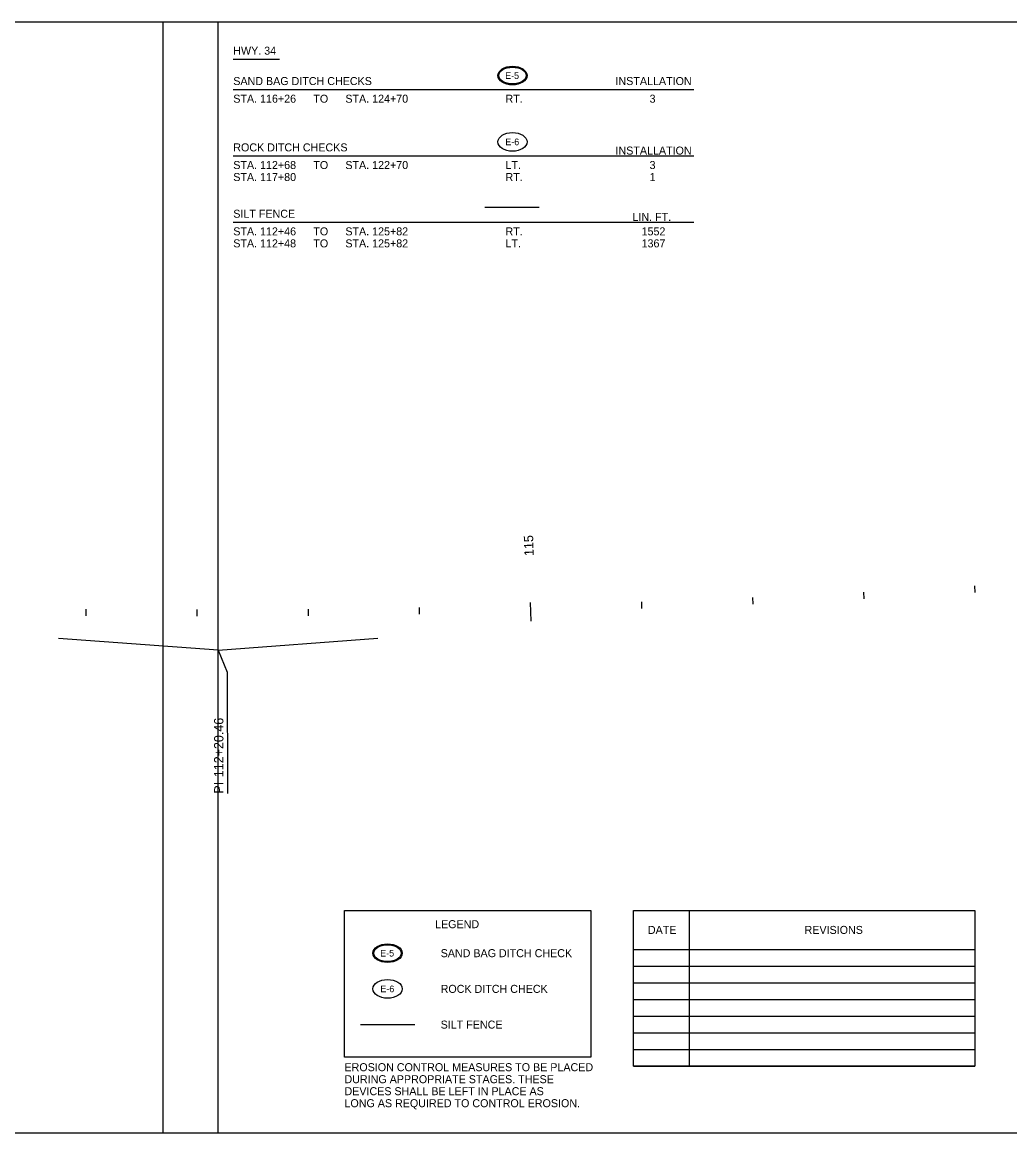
# Model space of a CAD drawing. Extents: x 1806834 to 1810084, y 678065 to 679314.
# Drawn here: x 1808308 to 1809196, y 678065 to 679065 of the extents above; entities that cross this region are included whole.
import ezdxf

# ---------------------------------------------------------------- set-up
doc = ezdxf.new("R2010")
doc.units = 0
for name, color, linetype in [('_CG DITCH CHECK', 7, 'Continuous'), ('Default', 7, 'Continuous'), ('DSN_DRFT_Guideline-No-Plot', 7, 'Continuous'), ('DSN_RDWY_Alignment Annotation', 7, 'Continuous'), ('Erosion Legend', 7, 'Continuous'), ('R_Border Notes', 7, 'Continuous')]:
    doc.layers.add(name, color=color, linetype=linetype)

# ---------------------------------------------------------------- blocks, each defined once
blk = doc.blocks.new('E-6')
at = {"layer": 'Default'}
blk.add_ellipse((0, 0), major_axis=(1.315, 0), ratio=0.638788, dxfattribs=at)
blk.add_text('E-6', height=0.6, dxfattribs=at).set_placement((-0.643, -0.3))

msp = doc.modelspace()

# ---------------------------------------------------------------- linework, layer by layer
at = {"layer": '_CG DITCH CHECK'}
for centre, major_axis, ratio in [((1808748.46, 679016.53), (13.15, 0), 0.638788), ((1808748.46, 679016.53), (-12.29, 0), 0.613481), ((1808636.1, 678227.04), (13.15, 0), 0.638788), ((1808636.1, 678227.04), (-12.29, 0), 0.613481)]:
    msp.add_ellipse(centre, major_axis=major_axis, ratio=ratio, dxfattribs=at)
at = {"layer": 'Default'}
for p, q in [((1808497.31, 679031.4), (1808538.99, 679031.4)), ((1808497.31, 679004.06), (1808911.66, 679004.06)), ((1808497.31, 678944.39), (1808911.66, 678944.39)), ((1808497.31, 678884.71), (1808911.66, 678884.71)), ((1808907.25, 678265.46), (1808907.25, 678125.46)), ((1808857.25, 678230.46), (1809164.27, 678230.46)), ((1808857.25, 678215.46), (1809164.27, 678215.46)), ((1808857.25, 678200.46), (1809164.27, 678200.46)), ((1808857.25, 678185.46), (1809164.27, 678185.46)), ((1808857.25, 678170.46), (1809164.27, 678170.46)), ((1808857.25, 678155.46), (1809164.27, 678155.46)), ((1808857.25, 678140.46), (1809164.27, 678140.46))]:
    msp.add_line(p, q, dxfattribs=at)
for points in [[(1808597.36, 678265.46), (1808818.86, 678265.46), (1808818.86, 678133.55), (1808597.36, 678133.55)], [(1808857.25, 678265.46), (1809164.27, 678265.46), (1809164.27, 678125.46), (1808857.25, 678125.46)]]:
    msp.add_lwpolyline(points, close=True, dxfattribs=at)
at = {"layer": 'DSN_DRFT_Guideline-No-Plot'}
for points in [[(1806833.89, 678065.46), (1808483.89, 678065.46), (1808483.89, 679064.52), (1806833.89, 679064.52)], [(1808433.89, 678065.46), (1810083.89, 678065.46), (1810083.89, 679064.52), (1808433.89, 679064.52)]]:
    msp.add_lwpolyline(points, close=True, dxfattribs=at)
at = {"layer": 'DSN_RDWY_Alignment Annotation'}
for p, q in [((1809064.06, 678551.71), (1809064.37, 678545.72)), ((1809163.85, 678557.35), (1809164.21, 678551.36)), ((1808764.39, 678542.42), (1808764.82, 678525.63)), ((1808864.35, 678543.05), (1808864.56, 678537.05)), ((1808964.22, 678546.94), (1808964.48, 678540.95)), ((1808364.7, 678536.65), (1808364.64, 678530.65)), ((1808464.64, 678536.18), (1808464.64, 678530.18)), ((1808564.59, 678536.59), (1808564.64, 678530.59)), ((1808664.53, 678537.87), (1808664.63, 678531.87)), ((1808483.67, 678499.71), (1808340.03, 678509.99)), ((1808483.67, 678499.71), (1808627.27, 678510.39)), ((1808483.67, 678499.71), (1808492, 678479.77)), ((1808492, 678479.77), (1808492.15, 678370.56)), ((1808483.83, 678379.71), (1808483.83, 678379.71))]:
    msp.add_line(p, q, dxfattribs=at)
at = {"layer": 'Erosion Legend'}
for p, q in [((1808723.63, 678898.09), (1808772.58, 678898.09)), ((1808611.63, 678162.8), (1808660.57, 678162.8))]:
    msp.add_line(p, q, dxfattribs=at)
at = {"layer": 'R_Border Notes'}
msp.add_line((1808857.25, 678125.46), (1809164.27, 678125.46), dxfattribs=at)

# ---------------------------------------------------------------- block references
at = {"layer": 'Erosion Legend', "xscale": 10, "yscale": 10, "rotation": -1.8065126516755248e-10}
for p in [(1808748.46, 678956.85), (1808636.1, 678194.92)]:
    msp.add_blockref('E-6', p, dxfattribs=at)

# ---------------------------------------------------------------- texts
at = {"layer": '_CG DITCH CHECK'}
for p in [(1808741.87, 679013.53), (1808629.51, 678224.04)]:
    msp.add_text('E-5', height=6, dxfattribs=at).set_placement(p)
at = {"layer": 'Default'}
for s, p in [('HWY. 34', (1808497.36, 679035.32)), ('SAND BAG DITCH CHECKS', (1808497.36, 679007.98)), ('INSTALLATION', (1808841.11, 679007.98)), ('STA. 116+26', (1808497.36, 678992.11)), ('TO ', (1808569.36, 678992.11)), ('STA. 124+70', (1808598.16, 678992.11)), ('RT.', (1808742.16, 678992.11)), ('3', (1808871.76, 678992.11)), ('ROCK DITCH CHECKS', (1808497.36, 678948.31)), ('INSTALLATION', (1808841.11, 678945.44)), ('STA. 112+68 ', (1808497.36, 678932.44)), ('TO ', (1808569.36, 678932.44)), ('STA. 122+70 ', (1808598.16, 678932.44)), ('LT.', (1808742.16, 678932.44)), ('3', (1808871.76, 678932.44)), ('STA. 117+80 ', (1808497.36, 678921.64)), ('RT.', (1808742.16, 678921.64)), ('1', (1808871.76, 678921.64)), ('SILT FENCE', (1808497.36, 678888.63)), ('LIN. FT.', (1808856.39, 678885.76)), ('STA. 112+46 ', (1808497.36, 678872.76)), ('TO ', (1808569.36, 678872.76)), ('STA. 125+82', (1808598.16, 678872.76)), ('RT.', (1808742.16, 678872.76)), ('1552', (1808864.56, 678872.76)), ('STA. 112+48 ', (1808497.36, 678861.96)), ('TO ', (1808569.36, 678861.96)), ('STA. 125+82', (1808598.16, 678861.96)), ('LT.', (1808742.16, 678861.96)), ('1367', (1808864.56, 678861.96)), ('LEGEND', (1808678.86, 678249.52)), ('DATE', (1808870.23, 678244.36)), ('REVISIONS', (1809011.16, 678244.36)), ('SAND BAG DITCH CHECK', (1808683.86, 678223.44)), ('ROCK DITCH CHECK', (1808683.86, 678191.32)), ('SILT FENCE', (1808683.86, 678159.2)), ('EROSION CONTROL MEASURES TO BE PLACED', (1808597.36, 678120.87)), ('DURING APPROPRIATE STAGES. THESE ', (1808597.36, 678110.07)), ('DEVICES SHALL BE LEFT IN PLACE AS ', (1808597.36, 678099.27)), ('LONG AS REQUIRED TO CONTROL EROSION.', (1808597.36, 678088.47))]:
    msp.add_text(s, height=7.2, dxfattribs=at).set_placement(p)
at = {"layer": 'DSN_RDWY_Alignment Annotation'}
for s, rotation, p in [('115', 91.48404, (1808767.5, 678584.46)), ('112+20.46', 90.07896, (1808488.53, 678385.37)), ('PI ', 90.07896, (1808488.55, 678370.56))]:
    msp.add_text(s, height=8.4, rotation=rotation, dxfattribs=at).set_placement(p)

doc.saveas('drawing.dxf')
